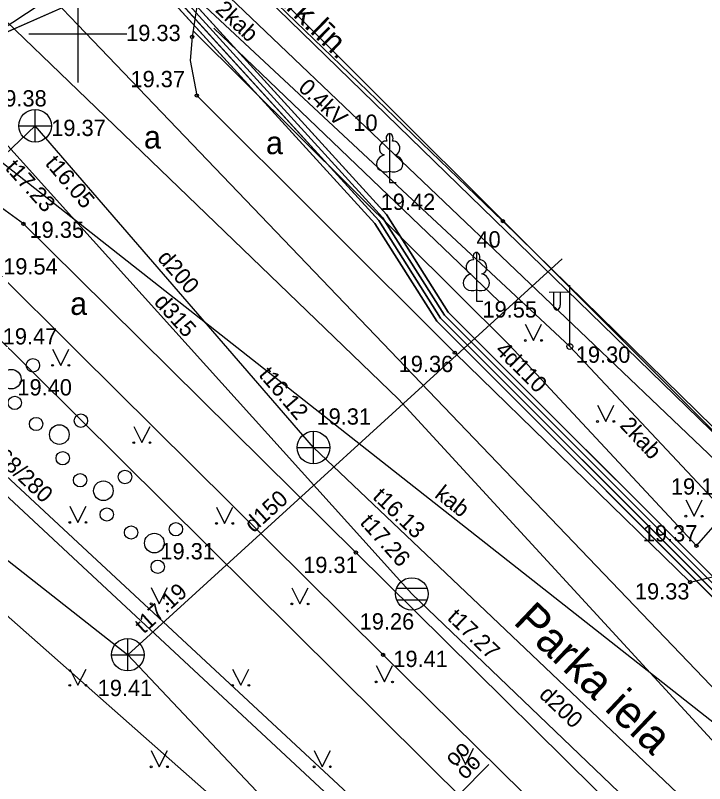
# Model space of a CAD drawing. Extents: x 532933 to 533143, y 328014 to 328163.
# Drawn here: x 532998.08 to 533019.24, y 328126.98 to 328150.56 of the extents above; entities that cross this region are included whole.
import ezdxf

# ---------------------------------------------------------------- set-up
doc = ezdxf.new("R2010")
doc.units = 0
for name, color, linetype in [('APGR_SARK_####_####_#', 7, 'Continuous'), ('APGR_SARK_####_TKST_#', 7, 'Continuous'), ('APGS_ELEM_####_####_#', 7, 'Continuous'), ('APGS_VADV_ZSPR_####_#', 7, 'Continuous'), ('APGS_VADV_ZSPR_TKST_#', 7, 'Continuous'), ('CELI_CAPM_####_####_#', 7, 'Continuous'), ('CELI_CMAL_####_####_#', 7, 'Continuous'), ('CELI_CSEG_####_TKST_#', 7, 'Continuous'), ('CELI_IELA_####_TKST_#', 7, 'Continuous'), ('ELEK_ACRL_####_####_#', 7, 'Continuous'), ('ELEK_ACRL_####_TKST_#', 7, 'Continuous'), ('ELEK_VADP_ZSPR_####_#', 7, 'Continuous'), ('GEOD_ELEM_####_####_#', 7, 'Continuous'), ('LKAN_ELEM_####_####_#', 7, 'Continuous'), ('LKAN_ELEM_PAST_TKST_#', 7, 'Continuous'), ('LKAN_VADP_PAST_####_#', 7, 'Continuous'), ('LKAN_VADP_PAST_TKST_#', 7, 'Continuous'), ('NORB_ZOGS_ZSTP_####_#', 7, 'Continuous'), ('RAMI_UZMR_####_####_#', 7, 'Continuous'), ('RELJ_AATZ_####_TKST_#', 7, 'Continuous'), ('RELJ_ELEM_####_####_#', 7, 'Continuous'), ('ROBZ_PROJ_####_####_#', 7, 'Continuous'), ('ROBZ_UZMR_####_####_#', 7, 'Continuous'), ('SAKK_ELEM_####_TKST_#', 7, 'Continuous'), ('SAKK_IZVK_####_TKST_#', 7, 'Continuous'), ('SAKK_KKAN_####_####_#', 7, 'Continuous'), ('SAKT_VADV_PKAB_####_#', 7, 'Continuous'), ('SAKT_VADV_PKAB_TKST_#', 7, 'Continuous'), ('SILT_VADP_UDEN_####_#', 7, 'Continuous'), ('SILT_VADP_UDEN_TKST_#', 7, 'Continuous'), ('SKAN_ELEM_####_####_#', 7, 'Continuous'), ('SKAN_ELEM_PAST_TKST_#', 7, 'Continuous'), ('SKAN_VADP_PAST_####_#', 7, 'Continuous'), ('SKAN_VADP_PAST_TKST_#', 7, 'Continuous'), ('TERT_DIAM_####_TKST_#', 7, 'Continuous'), ('TERT_ELEM_####_####_#', 7, 'Continuous'), ('TERT_KRND_####_####_#', 7, 'Continuous'), ('UDTK_VADP_UDEN_####_#', 7, 'Continuous')]:
    doc.layers.add(name, color=color, linetype=linetype)

msp = doc.modelspace()

# ---------------------------------------------------------------- linework, layer by layer
at = {"layer": 'APGR_SARK_####_####_#'}
for p, q in [((533005.074, 328151.787), (533020.89, 328136.408)), ((533025.763, 328107.492), (532984.275, 328144.093))]:
    msp.add_line(p, q, dxfattribs=at)
at = {"layer": 'APGS_ELEM_####_####_#'}
for p, q in [((533015.099, 328140.4), (533015.099, 328142.282)), ((533015.099, 328142.066), (533014.464, 328142.061)), ((533014.599, 328142.062), (533014.599, 328141.67)), ((533014.809, 328142.064), (533014.809, 328141.67))]:
    msp.add_line(p, q, dxfattribs=at)
msp.add_circle((533015.099, 328140.4), 0.09, dxfattribs=at)
msp.add_ellipse((533014.704, 328141.67), major_axis=(0, 0.151), ratio=0.695971, start_param=1.570796, end_param=4.712389, dxfattribs=at)
at = {"layer": 'APGS_VADV_ZSPR_####_#'}
for q in [(533001.112, 328153.446), (533035.157, 328119.006)]:
    msp.add_line((533015.099, 328140.4), q, dxfattribs=at)
at = {"layer": 'CELI_CAPM_####_####_#'}
for points in [[(533003.508, 328149.901), (533003.446, 328149.174), (533003.651, 328148.102), (533011.568, 328140.209), (533018.793, 328133.17), (533019.865, 328133.427), (533020.585, 328134.078)], [(533000, 328142.512), (532998.33, 328144.164), (532997.535, 328144.738)], [(533027.507, 328110.598), (533028.305, 328111.541), (533028.663, 328113.007), (533027.956, 328114.821), (533018.633, 328124.092), (533008.536, 328134.073), (533000, 328142.512)]]:
    msp.add_lwpolyline(points, dxfattribs=at)
at = {"layer": 'CELI_CMAL_####_####_#'}
for p, q in [((533004.04, 328153.304), (533003.508, 328149.901)), ((533003.537, 328150.086), (533013.24, 328140.453)), ((533013.24, 328140.453), (533018.988, 328134.285)), ((533018.988, 328134.285), (533020.941, 328136.515))]:
    msp.add_line(p, q, dxfattribs=at)
for points in [[(532980.078, 328132.911), (532996.503, 328142.518), (532997.446, 328142.761), (533000, 328140.228)], [(533000, 328140.228), (533009.371, 328130.936), (533020.128, 328120.334), (533028.429, 328112.049)]]:
    msp.add_lwpolyline(points, dxfattribs=at)
at = {"layer": 'ELEK_ACRL_####_####_#'}
for points in [[(533021.413, 328130.777), (533011.016, 328141.172), (533009.114, 328144.174), (533001.721, 328152.298), (533000.9, 328153.335)], [(533021.501, 328130.901), (533011.134, 328141.266), (533009.234, 328144.265), (533001.836, 328152.395), (533001.035, 328153.406)], [(533021.59, 328131.025), (533011.252, 328141.36), (533009.354, 328144.357), (533001.95, 328152.493), (533001.174, 328153.479)], [(533021.678, 328131.149), (533011.37, 328141.454), (533009.474, 328144.448), (533002.065, 328152.59), (533001.306, 328153.548)]]:
    msp.add_lwpolyline(points, dxfattribs=at)
at = {"layer": 'ELEK_VADP_ZSPR_####_#'}
for p, q in [((533001.836, 328152.395), (533009.234, 328144.265)), ((533001.95, 328152.493), (533009.354, 328144.357)), ((533002.065, 328152.59), (533009.474, 328144.448)), ((533001.721, 328152.298), (533009.114, 328144.174)), ((533009.474, 328144.448), (533011.37, 328141.454)), ((533009.114, 328144.174), (533011.016, 328141.172)), ((533009.234, 328144.265), (533011.134, 328141.266)), ((533009.354, 328144.357), (533011.252, 328141.36)), ((533011.252, 328141.36), (533021.59, 328131.025)), ((533011.37, 328141.454), (533021.678, 328131.149)), ((533011.016, 328141.172), (533021.413, 328130.777)), ((533011.134, 328141.266), (533021.501, 328130.901))]:
    msp.add_line(p, q, dxfattribs=at)
at = {"layer": 'GEOD_ELEM_####_####_#'}
for p, q in [((533000, 328151.5), (533000, 328150)), ((532998.5, 328150), (533000, 328150)), ((533000, 328150), (533000, 328148.5)), ((533000, 328150), (533001.5, 328150))]:
    msp.add_line(p, q, dxfattribs=at)
at = {"layer": 'LKAN_ELEM_####_####_#'}
for p, q in [((533009.784, 328132.979), (533010.72, 328132.979)), ((533009.784, 328132.629), (533010.72, 328132.629))]:
    msp.add_line(p, q, dxfattribs=at)
msp.add_circle((533010.252, 328132.804), 0.5, dxfattribs=at)
at = {"layer": 'LKAN_VADP_PAST_####_#'}
for points in [[(532997.292, 328147.175), (533000, 328144.172)], [(533000, 328144.172), (533010.252, 328132.804), (533025.892, 328117.826), (533035.077, 328109.135), (533038.53, 328105.77)]]:
    msp.add_lwpolyline(points, dxfattribs=at)
at = {"layer": 'NORB_ZOGS_ZSTP_####_#'}
msp.add_lwpolyline([(533020.996, 328136.461), (533013.046, 328144.246), (533005.031, 328151.966), (533005.896, 328152.718)], dxfattribs=at)
at = {"layer": 'RAMI_UZMR_####_####_#'}
msp.add_lwpolyline([(532947.854, 328059.458), (532970.012, 328105.269), (532980.164, 328130.66), (532983.041, 328140.509), (533003.397, 328153.917), (533034.71, 328122.623), (533045.001, 328112.629), (533020.332, 328088.009), (533039.378, 328069.977), (533029.682, 328029.753), (533016.724, 328021.343), (532947.854, 328059.458)], dxfattribs=at)
at = {"layer": 'RELJ_ELEM_####_####_#'}
for centre in [(533003.508, 328149.901), (533003.651, 328148.102), (532998.33, 328144.164), (533013.046, 328144.246), (533011.569, 328140.209), (533018.988, 328134.285), (533008.536, 328134.073), (533018.792, 328133.17), (533009.371, 328130.936)]:
    msp.add_circle(centre, 0.05, dxfattribs=at)
at = {"layer": 'ROBZ_PROJ_####_####_#'}
for p, q in [((532984.275, 328144.093), (533009.773, 328155.319)), ((533005.074, 328151.787), (533020.89, 328136.408)), ((533025.763, 328107.492), (532984.275, 328144.093))]:
    msp.add_line(p, q, dxfattribs=at)
at = {"layer": 'ROBZ_UZMR_####_####_#'}
msp.add_line((532984.275, 328144.093), (533025.763, 328107.492), dxfattribs=at)
msp.add_lwpolyline([(533007.012, 328157.979), (533009.773, 328155.319), (532984.275, 328144.093), (532980.744, 328150.912)], dxfattribs=at)
at = {"layer": 'SAKK_IZVK_####_TKST_#'}
msp.add_line((533011.691, 328126.639), (533012.612, 328127.567), dxfattribs=at)
at = {"layer": 'SAKK_KKAN_####_####_#'}
for points in [[(532997.218, 328140.997), (533000, 328138.237)], [(533000, 328138.237), (533026.568, 328111.881), (533036.477, 328102.895)]]:
    msp.add_lwpolyline(points, dxfattribs=at)
at = {"layer": 'SAKT_VADV_PKAB_####_#'}
msp.add_lwpolyline([(533043.676, 328109.828), (532992.415, 328150.168)], dxfattribs=at)
at = {"layer": 'SILT_VADP_UDEN_####_#'}
for points in [[(533000, 328134.38), (532990.882, 328142.854), (532990.898, 328143.294), (532995.193, 328147.364), (532995.204, 328147.787), (532994.06, 328149.035)], [(532993.817, 328148.807), (532994.69, 328147.849), (532994.66, 328147.396), (532990.285, 328143.304), (532990.328, 328142.785), (533000, 328133.784)], [(533004.853, 328045.947), (533019.384, 328034.966), (533019.749, 328035.185), (533031.003, 328047.839), (533031.356, 328048.225), (533031.335, 328048.654), (533025.793, 328053.779), (533025.755, 328054.215), (533035.838, 328064.377), (533036.105, 328064.808), (533033.176, 328075.216), (533032.836, 328076.021), (533015.446, 328091.145), (533015.462, 328091.585), (533029.065, 328106.172), (533029.033, 328106.692), (533017.302, 328118.3), (533000, 328134.38)], [(533000, 328133.784), (533016.764, 328118.182), (533028.476, 328106.559), (533028.508, 328106.039), (533014.85, 328091.596), (533014.892, 328091.077), (533032.527, 328075.724), (533032.689, 328075.239), (533035.542, 328065.283), (533035.311, 328064.711), (533024.98, 328054.226), (533025.028, 328053.821), (533027.938, 328051.227), (533030.653, 328048.689), (533030.642, 328048.162), (533019.754, 328035.526), (533019.215, 328035.483), (533005.473, 328047.022)]]:
    msp.add_lwpolyline(points, dxfattribs=at)
at = {"layer": 'SKAN_ELEM_####_####_#'}
for p, q in [((532998.689, 328146.673), (532998.689, 328147.673)), ((532998.189, 328147.173), (532999.189, 328147.173)), ((533007.233, 328136.797), (533007.233, 328137.797)), ((533006.733, 328137.297), (533007.733, 328137.297)), ((533001.531, 328130.44), (533001.531, 328131.44)), ((533001.031, 328130.94), (533002.031, 328130.94))]:
    msp.add_line(p, q, dxfattribs=at)
for centre in [(532998.689, 328147.173), (533007.233, 328137.297), (533001.531, 328130.94)]:
    msp.add_circle(centre, 0.5, dxfattribs=at)
at = {"layer": 'SKAN_VADP_PAST_####_#'}
for points in [[(533000, 328145.658), (532998.689, 328147.173), (532993.321, 328142.049), (532988.927, 328146.536)], [(533001.531, 328130.94), (533018.885, 328112.548), (533025.52, 328119.937), (533007.233, 328137.297), (533000, 328145.658)], [(532984.185, 328144.578), (533000, 328132.144)], [(533001.531, 328130.94), (533014.867, 328143.09)], [(533000, 328132.144), (533001.531, 328130.94)]]:
    msp.add_lwpolyline(points, dxfattribs=at)
at = {"layer": 'TERT_ELEM_####_####_#'}
for p, q in [((533009.569, 328145.782), (533009.569, 328145.435)), ((533009.569, 328145.435), (533009.769, 328145.435)), ((533012.235, 328142.134), (533012.235, 328141.787)), ((533012.235, 328141.787), (533012.435, 328141.787)), ((533013.735, 328141.084), (533013.985, 328140.584)), ((533013.985, 328140.584), (533014.235, 328141.084)), ((532999.225, 328140.321), (532999.475, 328139.821)), ((532999.475, 328139.821), (532999.725, 328140.321)), ((533015.953, 328138.6), (533016.203, 328138.1)), ((533016.203, 328138.1), (533016.453, 328138.6)), ((533001.715, 328137.948), (533001.965, 328137.448)), ((533001.965, 328137.448), (533002.215, 328137.948)), ((533018.663, 328135.691), (533018.913, 328135.191)), ((533018.913, 328135.191), (533019.163, 328135.691)), ((532999.75, 328135.5), (533000, 328135)), ((533000, 328135), (533000.25, 328135.5)), ((533004.256, 328135.47), (533004.506, 328134.97)), ((533004.506, 328134.97), (533004.756, 328135.47)), ((533002.25, 328133), (533002.5, 328132.5)), ((533002.5, 328132.5), (533002.75, 328133)), ((533006.567, 328132.997), (533006.817, 328132.497)), ((533006.817, 328132.497), (533007.067, 328132.997)), ((532999.75, 328130.5), (533000, 328130)), ((533000, 328130), (533000.25, 328130.5)), ((533004.75, 328130.5), (533005, 328130)), ((533005, 328130), (533005.25, 328130.5)), ((533009.158, 328130.604), (533009.408, 328130.104)), ((533009.408, 328130.104), (533009.658, 328130.604)), ((533002.25, 328128), (533002.5, 328127.5)), ((533002.5, 328127.5), (533002.75, 328128)), ((533007.25, 328128), (533007.5, 328127.5)), ((533007.5, 328127.5), (533007.75, 328128)), ((533011.649, 328128.067), (533011.899, 328127.567)), ((533011.899, 328127.567), (533012.149, 328128.067))]:
    msp.add_line(p, q, dxfattribs=at)
for points in [[(533009.569, 328146.935), (533009.569, 328145.782)], [(533009.659, 328146.702), (533009.658, 328146.703)], [(533012.235, 328143.287), (533012.235, 328142.134)], [(533012.324, 328143.055), (533012.323, 328143.055)]]:
    msp.add_lwpolyline(points, dxfattribs=at)
for centre, radius in [((533013.735, 328140.584), 0.028), ((533014.235, 328140.584), 0.0263), ((532998.62, 328139.82), 0.207), ((532997.958, 328139.396), 0.301), ((532999.224, 328139.821), 0.028), ((532999.724, 328139.821), 0.0263), ((532998.062, 328138.668), 0.205), ((533000.093, 328138.122), 0.207), ((532998.717, 328138.021), 0.204), ((533015.953, 328138.099), 0.028), ((533016.453, 328138.099), 0.0263), ((532999.431, 328137.697), 0.301), ((533001.715, 328137.448), 0.028), ((533002.215, 328137.448), 0.0263), ((532999.535, 328136.969), 0.205), ((533001.445, 328136.396), 0.207), ((533000.069, 328136.295), 0.204), ((533000.783, 328135.971), 0.301), ((533000.887, 328135.243), 0.205), ((533018.663, 328135.191), 0.028), ((533019.163, 328135.191), 0.0263), ((532999.75, 328135), 0.028), ((533000.25, 328135), 0.0263), ((533003.009, 328134.791), 0.207), ((533004.256, 328134.97), 0.028), ((533004.756, 328134.97), 0.0263), ((533001.633, 328134.69), 0.204), ((533002.348, 328134.366), 0.301), ((533002.451, 328133.638), 0.205), ((533002.25, 328132.5), 0.028), ((533002.75, 328132.5), 0.0263), ((533006.567, 328132.497), 0.028), ((533007.067, 328132.497), 0.0263), ((532999.75, 328130), 0.028), ((533000.25, 328130), 0.0263), ((533004.75, 328130), 0.028), ((533005.25, 328130), 0.0263), ((533009.158, 328130.104), 0.028), ((533009.658, 328130.104), 0.0263), ((533002.25, 328127.5), 0.028), ((533002.75, 328127.5), 0.0263), ((533007.25, 328127.5), 0.028), ((533007.75, 328127.5), 0.0263), ((533011.648, 328127.566), 0.028), ((533012.148, 328127.566), 0.0263)]:
    msp.add_circle(centre, radius, dxfattribs=at)
for centre, major_axis, ratio, start_param, end_param in [((533009.57, 328146.785), (0, -0.15), 0.707107, 3.14537, 5.287485), ((533009.569, 328146.785), (0, -0.15), 0.707107, 0.995701, 3.137816), ((533009.441, 328146.49), (-0.039, -0.212), 0.861323, 3.141593, 6.283185), ((533009.697, 328146.49), (0.039, -0.212), 0.861323, 0, 3.141593), ((533009.48, 328146.028), (0.307, 0.095), 0.814445, 1.570796, 4.752015), ((533009.659, 328146.028), (-0.307, 0.095), 0.814445, 1.531171, 4.712389), ((533012.235, 328143.137), (0, -0.15), 0.707107, 3.14537, 5.287485), ((533012.234, 328143.137), (0, -0.15), 0.707107, 0.995701, 3.137816), ((533012.106, 328142.842), (-0.039, -0.212), 0.861323, 3.141593, 6.283185), ((533012.363, 328142.842), (0.039, -0.212), 0.861323, 0, 3.141593), ((533012.145, 328142.38), (0.307, 0.095), 0.814445, 1.570796, 4.752015), ((533012.324, 328142.38), (-0.307, 0.095), 0.814445, 1.531171, 4.712389)]:
    msp.add_ellipse(centre, major_axis=major_axis, ratio=ratio, start_param=start_param, end_param=end_param, dxfattribs=at)
at = {"layer": 'TERT_KRND_####_####_#'}
msp.add_line((533020.193, 328136.302), (533004.117, 328151.633), dxfattribs=at)
msp.add_lwpolyline([(533012.919, 328141.789), (533004.172, 328150.164)], dxfattribs=at)
at = {"layer": 'UDTK_VADP_UDEN_####_#'}
for p, q in [((532996.906, 328151.243), (533000, 328148.264)), ((533000, 328148.264), (533009.846, 328138.784)), ((533009.846, 328138.784), (533026.302, 328120.883))]:
    msp.add_line(p, q, dxfattribs=at)
for points in [[(533000, 328150.276), (532998.349, 328151.999)], [(533010.744, 328081.458), (533040.624, 328109.383), (533024.808, 328124.378), (533000, 328150.276)]]:
    msp.add_lwpolyline(points, dxfattribs=at)

# ---------------------------------------------------------------- texts
at = {"layer": 'APGR_SARK_####_TKST_#'}
msp.add_text('sark.līn.', height=0.7, rotation=315.8026, dxfattribs=at).set_placement((533005.651, 328151.454))
at = {"layer": 'APGS_VADV_ZSPR_TKST_#'}
for s, rotation, p in [('2kab', 316.9922, (533004.191, 328150.699)), ('0.4kV', 316.9922, (533006.735, 328148.298)), ('2kab', 313.154, (533016.609, 328137.955))]:
    msp.add_text(s, height=0.5, rotation=rotation, dxfattribs=at).set_placement(p)
at = {"layer": 'CELI_CSEG_####_TKST_#'}
for p in [(533002.028, 328146.475), (533005.773, 328146.302), (532999.764, 328141.369)]:
    msp.add_text('a', height=0.7, dxfattribs=at).set_placement(p)
at = {"layer": 'CELI_IELA_####_TKST_#'}
msp.add_text('Parka iela', height=1, rotation=316.4899, dxfattribs=at).set_placement((533013.336, 328131.916))
at = {"layer": 'ELEK_ACRL_####_TKST_#'}
msp.add_text('4d110', height=0.5, rotation=315.0077, dxfattribs=at).set_placement((533012.783, 328140.253))
at = {"layer": 'LKAN_ELEM_PAST_TKST_#'}
for s, p in [(' 19.38', (532997.184, 328147.765)), (' 19.26', (533008.465, 328131.713))]:
    msp.add_text(s, height=0.5, dxfattribs=at).set_placement(p)
at = {"layer": 'LKAN_VADP_PAST_TKST_#'}
for s, rotation, p in [('t17.23', 311.931, (532997.743, 328145.86)), ('d315', 311.931, (533002.311, 328141.746)), ('t17.26', 311.931, (533008.635, 328134.979)), ('t17.27', 316.2583, (533011.311, 328132.041))]:
    msp.add_text(s, height=0.5, rotation=rotation, dxfattribs=at).set_placement(p)
at = {"layer": 'RELJ_AATZ_####_TKST_#'}
for s, p in [(' 19.33', (533001.297, 328149.773)), (' 19.37', (533001.428, 328148.357)), (' 19.42', (533009.11, 328144.591)), (' 19.35', (532998.33, 328143.734)), (' 19.54', (532997.522, 328142.609)), (' 19.55', (533012.235, 328141.287)), (' 19.30', (533015.099, 328139.9)), (' 19.36', (533009.662, 328139.615)), (' 19.40', (532997.958, 328138.896)), (' 19.18', (533018.017, 328135.852)), (' 19.37', (533017.156, 328134.416)), (' 19.31', (533002.348, 328133.866)), (' 19.31', (533006.731, 328133.447)), (' 19.33', (533016.914, 328132.635)), (' 19.41', (533009.498, 328130.562))]:
    msp.add_text(s, height=0.5, dxfattribs=at).set_placement(p)
at = {"layer": 'SAKK_ELEM_####_TKST_#'}
msp.add_text(' 19.47', height=0.5, dxfattribs=at).set_placement((532997.508, 328140.461))
at = {"layer": 'SAKK_IZVK_####_TKST_#'}
for p in [(533011.555, 328127.482), (533011.891, 328127.078)]:
    msp.add_text('oo', height=0.5, rotation=45.2295, dxfattribs=at).set_placement(p)
at = {"layer": 'SAKT_VADV_PKAB_TKST_#'}
msp.add_text('kab', height=0.5, rotation=321.799, dxfattribs=at).set_placement((533010.922, 328135.795))
at = {"layer": 'SILT_VADP_UDEN_TKST_#'}
msp.add_text('2d168/280', height=0.5, rotation=317.0965, dxfattribs=at).set_placement((532996.629, 328137.718))
at = {"layer": 'SKAN_ELEM_PAST_TKST_#'}
for s, p in [(' 19.37', (532998.997, 328146.859)), (' 19.31', (533007.14, 328138.001)), (' 19.41', (533000.423, 328129.67))]:
    msp.add_text(s, height=0.5, dxfattribs=at).set_placement(p)
at = {"layer": 'SKAN_VADP_PAST_TKST_#'}
for s, rotation, p in [('t16.05', 310.5182, (532998.971, 328146.004)), ('d200', 310.8622, (533002.416, 328143.094)), ('t16.12', 310.5182, (533005.528, 328139.515)), ('d150', 42.3354, (533005.392, 328134.66)), ('t16.13', 316.3862, (533009.018, 328135.752)), ('t17.19', 42.2471, (533002.022, 328131.56)), ('d200', 316.3862, (533014.128, 328129.672))]:
    msp.add_text(s, height=0.5, rotation=rotation, dxfattribs=at).set_placement(p)
at = {"layer": 'TERT_DIAM_####_TKST_#'}
for s, p in [('10', (533008.456, 328147.017)), ('40', (533012.235, 328143.437))]:
    msp.add_text(s, height=0.5, dxfattribs=at).set_placement(p)

doc.saveas('drawing.dxf')
